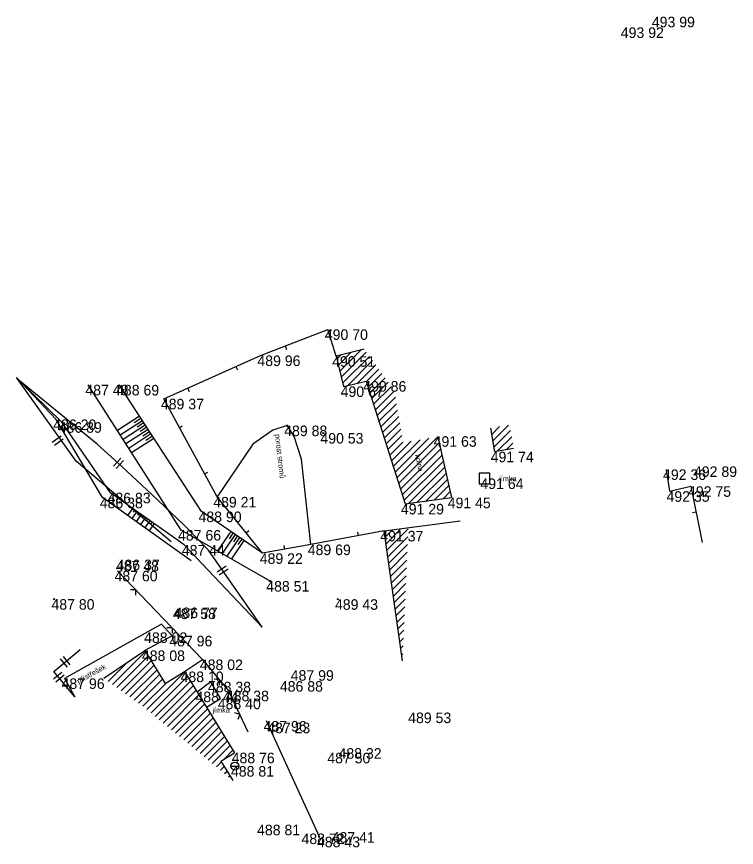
# Model space of a CAD drawing. Extents: x -553666 to -553461, y -1076543 to -1076230.
# Drawn here: x -553529.6 to -553461.3, y -1076543.4 to -1076464.6 of the extents above; entities that cross this region are included whole.
import ezdxf

# ---------------------------------------------------------------- set-up
doc = ezdxf.new("R2010")
doc.units = 0
for name, color, linetype in [('1', 7, 'Continuous'), ('12', 7, 'Continuous'), ('14', 7, 'Continuous'), ('18', 7, 'Continuous'), ('26', 7, 'Continuous'), ('27', 7, 'Continuous'), ('28', 7, 'Continuous'), ('32', 7, 'Continuous'), ('34', 7, 'Continuous'), ('50', 7, 'Continuous'), ('52', 7, 'Continuous'), ('6', 7, 'Continuous'), ('62', 7, 'Continuous')]:
    doc.layers.add(name, color=color, linetype=linetype)

# ---------------------------------------------------------------- blocks, each defined once
blk = doc.blocks.new('POINT_DISPLAY')
blk.add_line((0, 0), (0, 0))
blk = doc.blocks.new('T')
at = {"layer": '6'}
blk.add_circle((0, 0), 0.05, dxfattribs=at)
blk = doc.blocks.new('ST')
at = {"layer": '1'}
blk.add_line((-0.375, 0), (0.375, 0), dxfattribs=at)
blk.add_circle((0, 0), 0.375, dxfattribs=at)
blk = doc.blocks.new('SA')
at = {"layer": '50'}
blk.add_lwpolyline([(-0.5, -0.5), (0.5, -0.5), (0.5, 0.5), (-0.5, 0.5)], close=True, dxfattribs=at)
blk = doc.blocks.new('ROV')
at = {"layer": '62'}
for p, q in [((-0.348, -0.51), (-0.348, 0.51)), ((0, -0.51), (0, 0.51))]:
    blk.add_line(p, q, dxfattribs=at)

msp = doc.modelspace()

# ---------------------------------------------------------------- linework, layer by layer
at = {"layer": '12'}
for p, q in [((-553506.44, -1076496.75), (-553500.06, -1076494.27)), ((-553499.26, -1076496.82), (-553500.06, -1076494.27)), ((-553500.008, -1076494.435), (-553499.674, -1076494.33)), ((-553504.11, -1076495.844), (-553503.983, -1076496.17)), ((-553515.63, -1076500.86), (-553506.44, -1076496.75)), ((-553508.783, -1076497.798), (-553508.641, -1076498.118)), ((-553513.348, -1076499.839), (-553513.205, -1076500.159)), ((-553510.55, -1076510.17), (-553515.63, -1076500.86)), ((-553514.142, -1076503.586), (-553513.835, -1076503.419)), ((-553511.747, -1076507.975), (-553511.44, -1076507.808)), ((-553467.94, -1076507.56), (-553467.62, -1076509.63)), ((-553467.62, -1076509.63), (-553465.58, -1076509.16)), ((-553465.58, -1076509.16), (-553464.513, -1076514.499)), ((-553506.24, -1076515.52), (-553510.55, -1076510.17)), ((-553465.09, -1076511.612), (-553465.433, -1076511.68)), ((-553507.808, -1076513.573), (-553507.536, -1076513.354)), ((-553494.69, -1076513.39), (-553501.66, -1076514.69)), ((-553497.148, -1076513.848), (-553497.212, -1076513.504)), ((-553501.66, -1076514.69), (-553506.24, -1076515.52)), ((-553504.12, -1076515.136), (-553504.182, -1076514.791)), ((-553520.03, -1076517.18), (-553511.94, -1076525.6)), ((-553518.298, -1076518.983), (-553518.798, -1076518.973)), ((-553518.298, -1076518.983), (-553518.308, -1076519.483)), ((-553514.834, -1076522.588), (-553515.334, -1076522.578)), ((-553514.834, -1076522.588), (-553514.844, -1076523.089)), ((-553513.66, -1076526.74), (-553511.94, -1076525.6)), ((-553511.94, -1076525.6), (-553509.47, -1076528.56)), ((-553510.338, -1076527.519), (-553510.837, -1076527.474)), ((-553510.338, -1076527.519), (-553510.383, -1076528.018)), ((-553509.47, -1076528.56), (-553507.66, -1076532.46)), ((-553508.418, -1076530.828), (-553508.888, -1076530.656)), ((-553508.418, -1076530.828), (-553508.59, -1076531.298))]:
    msp.add_line(p, q, dxfattribs=at)
at = {"layer": '14'}
for p, q in [((-553496.592, -1076496.158), (-553499.26, -1076496.82)), ((-553499.26, -1076496.82), (-553498.55, -1076499.68)), ((-553498.55, -1076499.68), (-553496.4, -1076499.18)), ((-553496.4, -1076499.18), (-553492.72, -1076510.83)), ((-553484.594, -1076503.634), (-553484.22, -1076505.88)), ((-553489.597, -1076504.468), (-553488.3, -1076510.24)), ((-553482.409, -1076505.578), (-553484.22, -1076505.88)), ((-553492.72, -1076510.83), (-553488.3, -1076510.24)), ((-553494.69, -1076513.39), (-553487.47, -1076512.44)), ((-553492.965, -1076525.737), (-553494.69, -1076513.39)), ((-553521.317, -1076527.375), (-553517.44, -1076524.74)), ((-553517.44, -1076524.74), (-553515.504, -1076527.878)), ((-553515.504, -1076527.878), (-553513.66, -1076526.74)), ((-553513.66, -1076526.74), (-553508.91, -1076534.44)), ((-553510.204, -1076535.238), (-553508.91, -1076534.44)), ((-553510.204, -1076535.238), (-553509.081, -1076537.062))]:
    msp.add_line(p, q, dxfattribs=at)
at = {"layer": '18'}
for p, q in [((-553515.834, -1076522.24), (-553525.05, -1076527.39)), ((-553514.82, -1076523.35), (-553515.834, -1076522.24)), ((-553514.82, -1076523.35), (-553517.44, -1076524.74)), ((-553525.05, -1076527.39), (-553524.07, -1076529.13)), ((-553511.17, -1076527.71), (-553512.453, -1076528.696)), ((-553510.25, -1076529.31), (-553511.17, -1076527.71)), ((-553511.572, -1076530.125), (-553510.25, -1076529.31))]:
    msp.add_line(p, q, dxfattribs=at)
at = {"layer": '26'}
for p, q in [((-553517.933, -1076502.518), (-553520.031, -1076503.883)), ((-553517.796, -1076502.727), (-553518.426, -1076503.137)), ((-553517.66, -1076502.937), (-553519.761, -1076504.304)), ((-553517.387, -1076503.356), (-553519.491, -1076504.725)), ((-553517.524, -1076503.146), (-553518.154, -1076503.557)), ((-553517.251, -1076503.566), (-553517.883, -1076503.977)), ((-553517.115, -1076503.775), (-553519.222, -1076505.146)), ((-553516.842, -1076504.194), (-553518.952, -1076505.567)), ((-553516.978, -1076503.985), (-553517.611, -1076504.396)), ((-553516.569, -1076504.613), (-553518.682, -1076505.988)), ((-553516.706, -1076504.404), (-553517.339, -1076504.816)), ((-553518.591, -1076511.262), (-553519.062, -1076511.929)), ((-553518.387, -1076511.406), (-553518.529, -1076511.607)), ((-553518.183, -1076511.551), (-553518.655, -1076512.219)), ((-553517.774, -1076511.839), (-553518.247, -1076512.51)), ((-553517.978, -1076511.695), (-553518.12, -1076511.896)), ((-553517.366, -1076512.127), (-553517.841, -1076512.799)), ((-553517.57, -1076511.983), (-553517.712, -1076512.184)), ((-553516.957, -1076512.416), (-553517.433, -1076513.09)), ((-553517.162, -1076512.272), (-553517.304, -1076512.473)), ((-553516.549, -1076512.704), (-553517.026, -1076513.38)), ((-553516.753, -1076512.56), (-553516.896, -1076512.762)), ((-553509.263, -1076513.459), (-553510.516, -1076515.297)), ((-553508.85, -1076513.741), (-553510.081, -1076515.547)), ((-553509.057, -1076513.6), (-553509.429, -1076514.147)), ((-553508.437, -1076514.023), (-553509.645, -1076515.796)), ((-553508.024, -1076514.304), (-553509.21, -1076516.044)), ((-553508.644, -1076513.882), (-553509.009, -1076514.419)), ((-553508.23, -1076514.163), (-553508.59, -1076514.69))]:
    msp.add_line(p, q, dxfattribs=at)
at = {"layer": '27'}
for p, q in [((-553525.31, -1076503.08), (-553529.35, -1076499.11)), ((-553513.99, -1076513.31), (-553522.82, -1076499.53)), ((-553512.05, -1076511.56), (-553519.87, -1076499.54)), ((-553520.69, -1076509.78), (-553525.31, -1076503.08)), ((-553513.68, -1076514.73), (-553520.69, -1076509.78)), ((-553506.24, -1076515.52), (-553512.05, -1076511.56)), ((-553505.53, -1076518.15), (-553513.99, -1076513.31)), ((-553506.27, -1076522.52), (-553513.68, -1076514.73)), ((-553500.83, -1076542.41), (-553505.87, -1076531.43))]:
    msp.add_line(p, q, dxfattribs=at)
at = {"layer": '28'}
for p, q in [((-553525.85, -1076502.82), (-553529.6, -1076498.84)), ((-553521.43, -1076510.24), (-553525.85, -1076502.82)), ((-553513.03, -1076516.23), (-553521.43, -1076510.24))]:
    msp.add_line(p, q, dxfattribs=at)
at = {"layer": '32'}
for p, q in [((-553499.052, -1076497.659), (-553497.867, -1076496.474)), ((-553498.911, -1076498.226), (-553496.926, -1076496.241)), ((-553498.77, -1076498.792), (-553496.4, -1076496.422)), ((-553499.192, -1076497.093), (-553498.807, -1076496.708)), ((-553498.63, -1076499.359), (-553496.102, -1076496.831)), ((-553498.151, -1076499.587), (-553495.804, -1076497.24)), ((-553497.23, -1076499.373), (-553495.507, -1076497.65)), ((-553496.383, -1076499.233), (-553495.209, -1076498.059)), ((-553496.213, -1076499.771), (-553494.911, -1076498.468)), ((-553496.044, -1076500.308), (-553494.613, -1076498.877)), ((-553495.874, -1076500.845), (-553494.315, -1076499.287)), ((-553495.704, -1076501.383), (-553494.017, -1076499.696)), ((-553495.534, -1076501.92), (-553493.728, -1076500.113)), ((-553495.365, -1076502.458), (-553493.627, -1076500.72)), ((-553495.195, -1076502.995), (-553493.526, -1076501.326)), ((-553495.025, -1076503.532), (-553493.425, -1076501.932)), ((-553494.855, -1076504.07), (-553493.324, -1076502.538)), ((-553494.686, -1076504.607), (-553493.223, -1076503.144)), ((-553484.493, -1076504.24), (-553483.745, -1076503.492)), ((-553484.392, -1076504.846), (-553482.897, -1076503.351)), ((-553494.516, -1076505.144), (-553493.122, -1076503.75)), ((-553494.346, -1076505.682), (-553493.021, -1076504.356)), ((-553484.291, -1076505.453), (-553482.696, -1076503.857)), ((-553494.176, -1076506.219), (-553492.92, -1076504.962)), ((-553494.007, -1076506.756), (-553492.142, -1076504.892)), ((-553493.837, -1076507.294), (-553491.294, -1076504.751)), ((-553493.667, -1076507.831), (-553490.445, -1076504.609)), ((-553493.498, -1076508.369), (-553489.597, -1076504.468)), ((-553493.328, -1076508.906), (-553489.467, -1076505.045)), ((-553483.97, -1076505.838), (-553482.595, -1076504.463)), ((-553483.121, -1076505.697), (-553482.494, -1076505.069)), ((-553493.158, -1076509.443), (-553489.338, -1076505.623)), ((-553492.988, -1076509.981), (-553489.208, -1076506.2)), ((-553492.819, -1076510.518), (-553489.078, -1076506.777)), ((-553492.378, -1076510.784), (-553488.948, -1076507.355)), ((-553491.562, -1076510.675), (-553488.819, -1076507.932)), ((-553490.746, -1076510.566), (-553488.689, -1076508.51)), ((-553489.93, -1076510.458), (-553488.559, -1076509.087)), ((-553489.114, -1076510.349), (-553488.429, -1076509.664)), ((-553494.606, -1076513.989), (-553493.948, -1076513.331)), ((-553494.52, -1076514.61), (-553493.179, -1076513.269)), ((-553494.433, -1076515.23), (-553492.411, -1076513.208)), ((-553494.346, -1076515.85), (-553492.444, -1076513.948)), ((-553494.26, -1076516.471), (-553492.476, -1076514.688)), ((-553494.173, -1076517.091), (-553492.509, -1076515.427)), ((-553494.086, -1076517.712), (-553492.542, -1076516.167)), ((-553494, -1076518.332), (-553492.575, -1076516.907)), ((-553493.913, -1076518.953), (-553492.607, -1076517.647)), ((-553493.826, -1076519.573), (-553492.64, -1076518.387)), ((-553493.74, -1076520.193), (-553492.673, -1076519.127)), ((-553493.653, -1076520.814), (-553492.705, -1076519.866)), ((-553493.566, -1076521.434), (-553492.738, -1076520.606)), ((-553493.479, -1076522.055), (-553492.771, -1076521.346)), ((-553493.393, -1076522.675), (-553492.804, -1076522.086)), ((-553493.306, -1076523.295), (-553492.836, -1076522.826)), ((-553493.219, -1076523.916), (-553492.869, -1076523.565)), ((-553520.495, -1076527.967), (-553517.374, -1076524.847)), ((-553493.133, -1076524.536), (-553492.902, -1076524.305)), ((-553520.083, -1076528.263), (-553517.104, -1076525.284)), ((-553493.046, -1076525.157), (-553492.934, -1076525.045)), ((-553520.906, -1076527.671), (-553519.11, -1076525.875)), ((-553519.672, -1076528.558), (-553516.835, -1076525.721)), ((-553519.261, -1076528.854), (-553516.565, -1076526.158)), ((-553518.85, -1076529.15), (-553516.295, -1076526.596)), ((-553518.438, -1076529.446), (-553516.025, -1076527.033)), ((-553517.223, -1076530.352), (-553513.641, -1076526.77)), ((-553516.835, -1076530.671), (-553513.371, -1076527.208)), ((-553518.027, -1076529.742), (-553515.755, -1076527.47)), ((-553517.616, -1076530.038), (-553515.379, -1076527.801)), ((-553516.447, -1076530.991), (-553513.102, -1076527.645)), ((-553516.06, -1076531.31), (-553512.832, -1076528.082)), ((-553515.672, -1076531.63), (-553512.562, -1076528.52)), ((-553515.284, -1076531.949), (-553512.292, -1076528.957)), ((-553514.897, -1076532.269), (-553512.023, -1076529.394)), ((-553514.509, -1076532.588), (-553511.753, -1076529.832)), ((-553514.122, -1076532.908), (-553511.483, -1076530.269)), ((-553513.734, -1076533.227), (-553511.213, -1076530.706)), ((-553513.346, -1076533.546), (-553510.943, -1076531.144)), ((-553512.959, -1076533.866), (-553510.674, -1076531.581)), ((-553512.571, -1076534.185), (-553510.404, -1076532.018)), ((-553512.183, -1076534.505), (-553510.134, -1076532.456)), ((-553511.796, -1076534.824), (-553509.864, -1076532.893)), ((-553511.408, -1076535.144), (-553509.595, -1076533.33)), ((-553511.021, -1076535.463), (-553509.325, -1076533.768)), ((-553509.902, -1076535.052), (-553509.055, -1076534.205)), ((-553510.633, -1076535.783), (-553510.16, -1076535.31)), ((-553510.245, -1076536.102), (-553509.89, -1076535.747)), ((-553509.858, -1076536.422), (-553509.621, -1076536.185)), ((-553509.47, -1076536.741), (-553509.351, -1076536.623)), ((-553509.082, -1076537.061), (-553509.082, -1076537.06))]:
    msp.add_line(p, q, dxfattribs=at)
at = {"layer": '34'}
for points in [[(-553503.92, -1076503.4), (-553505.28, -1076503.851), (-553507.164, -1076505.162), (-553510.55, -1076510.17)], [(-553501.66, -1076514.69), (-553502.548, -1076506.582), (-553503.258, -1076504.452), (-553503.92, -1076503.4)]]:
    msp.add_lwpolyline(points, dxfattribs=at)
at = {"layer": '62'}
for p, q in [((-553523.93, -1076506.79), (-553529.6, -1076498.84)), ((-553521.94, -1076505.15), (-553529.35, -1076499.11)), ((-553519.6, -1076507.279), (-553521.94, -1076505.15)), ((-553514.917, -1076514.416), (-553523.93, -1076506.79)), ((-553516.751, -1076509.93), (-553519.6, -1076507.279)), ((-553513.789, -1076512.751), (-553516.751, -1076509.93)), ((-553511.37, -1076515.22), (-553513.789, -1076512.751)), ((-553506.27, -1076522.52), (-553511.37, -1076515.22)), ((-553526.06, -1076526.72), (-553523.561, -1076524.657)), ((-553524.07, -1076529.13), (-553526.06, -1076526.72))]:
    msp.add_line(p, q, dxfattribs=at)

# ---------------------------------------------------------------- block references
at = {"layer": '1'}
for name, p in [('POINT_DISPLAY', (-553468.99, -1076464.61)), ('POINT_DISPLAY', (-553471.95, -1076465.62)), ('POINT_DISPLAY', (-553500.06, -1076494.27)), ('POINT_DISPLAY', (-553506.44, -1076496.75)), ('POINT_DISPLAY', (-553499.26, -1076496.82)), ('POINT_DISPLAY', (-553522.82, -1076499.53)), ('POINT_DISPLAY', (-553519.87, -1076499.54)), ('POINT_DISPLAY', (-553496.4, -1076499.18)), ('POINT_DISPLAY', (-553498.55, -1076499.68)), ('POINT_DISPLAY', (-553515.63, -1076500.86)), ('POINT_DISPLAY', (-553525.85, -1076502.82)), ('POINT_DISPLAY', (-553525.31, -1076503.08)), ('POINT_DISPLAY', (-553503.92, -1076503.4)), ('POINT_DISPLAY', (-553500.48, -1076504.11)), ('POINT_DISPLAY', (-553492.87, -1076504.98)), ('POINT_DISPLAY', (-553489.61, -1076504.41)), ('POINT_DISPLAY', (-553484.22, -1076505.88)), ('POINT_DISPLAY', (-553465, -1076507.27)), ('POINT_DISPLAY', (-553467.94, -1076507.56)), ('POINT_DISPLAY', (-553485.18, -1076508.42)), ('POINT_DISPLAY', (-553520.69, -1076509.78)), ('POINT_DISPLAY', (-553467.62, -1076509.63)), ('POINT_DISPLAY', (-553465.58, -1076509.16)), ('POINT_DISPLAY', (-553521.43, -1076510.24)), ('POINT_DISPLAY', (-553510.55, -1076510.17)), ('POINT_DISPLAY', (-553488.3, -1076510.24)), ('POINT_DISPLAY', (-553492.72, -1076510.83)), ('POINT_DISPLAY', (-553512.05, -1076511.56)), ('POINT_DISPLAY', (-553513.99, -1076513.31)), ('POINT_DISPLAY', (-553494.69, -1076513.39)), ('POINT_DISPLAY', (-553513.68, -1076514.73)), ('POINT_DISPLAY', (-553501.66, -1076514.69)), ('POINT_DISPLAY', (-553519.83, -1076516.12)), ('POINT_DISPLAY', (-553506.24, -1076515.52)), ('POINT_DISPLAY', (-553519.93, -1076516.24)), ('POINT_DISPLAY', (-553520.03, -1076517.18)), ('POINT_DISPLAY', (-553505.53, -1076518.15)), ('POINT_DISPLAY', (-553526.03, -1076519.87)), ('POINT_DISPLAY', (-553499.11, -1076519.88)), ('POINT_DISPLAY', (-553514.51, -1076520.76)), ('POINT_DISPLAY', (-553514.33, -1076520.67)), ('POINT_DISPLAY', (-553517.23, -1076523.02)), ('POINT_DISPLAY', (-553514.82, -1076523.35)), ('POINT_DISPLAY', (-553517.44, -1076524.74)), ('POINT_DISPLAY', (-553511.94, -1076525.6)), ('POINT_DISPLAY', (-553513.66, -1076526.74)), ('POINT_DISPLAY', (-553503.29, -1076526.61)), ('POINT_DISPLAY', (-553525.05, -1076527.39)), ('POINT_DISPLAY', (-553511.17, -1076527.71)), ('POINT_DISPLAY', (-553504.33, -1076527.65)), ('POINT_DISPLAY', (-553512.38, -1076528.64)), ('POINT_DISPLAY', (-553509.47, -1076528.56)), ('POINT_DISPLAY', (-553510.25, -1076529.31)), ('POINT_DISPLAY', (-553492.15, -1076530.63)), ('POINT_DISPLAY', (-553505.87, -1076531.43)), ('POINT_DISPLAY', (-553505.55, -1076531.59)), ('POINT_DISPLAY', (-553498.77, -1076534.01)), ('POINT_DISPLAY', (-553508.91, -1076534.44)), ('POINT_DISPLAY', (-553499.84, -1076534.45)), ('ST', (-553508.88, -1076535.71)), ('POINT_DISPLAY', (-553508.88, -1076535.71)), ('POINT_DISPLAY', (-553506.4, -1076541.27)), ('POINT_DISPLAY', (-553502.29, -1076542.11)), ('POINT_DISPLAY', (-553499.33, -1076541.98)), ('POINT_DISPLAY', (-553500.83, -1076542.41))]:
    msp.add_blockref(name, p, dxfattribs=at)
at = {"layer": '32'}
for p in [(-553484.594, -1076503.634), (-553489.597, -1076504.468), (-553492.411, -1076513.208), (-553521.317, -1076527.375)]:
    msp.add_blockref('POINT_DISPLAY', p, dxfattribs=at)
at = {"layer": '50'}
msp.add_blockref('SA', (-553485.18, -1076508.42), dxfattribs=at)
at = {"layer": '6'}
for p in [(-553503.92, -1076503.4), (-553500.48, -1076504.11), (-553505.53, -1076518.15), (-553526.03, -1076519.87), (-553499.11, -1076519.88)]:
    msp.add_blockref('T', p, dxfattribs=at)
at = {"layer": '62'}
for p, xscale, yscale, rotation in [((-553525.796, -1076504.71), 1.000001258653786, 1.0000012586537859, 125.49673748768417), ((-553519.793, -1076507.103), 0.9999980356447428, 0.9999980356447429, -42.29682302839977), ((-553509.937, -1076517.271), 1.000001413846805, 1.000001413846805, -55.06074372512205), ((-553524.834, -1076525.708), 1.0000002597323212, 1.0000002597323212, 39.54061871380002), ((-553525.707, -1076527.148), 1.0000021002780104, 1.0000021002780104, 129.5474514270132)]:
    msp.add_blockref('ROV', p, dxfattribs=dict(at, xscale=xscale, yscale=yscale, rotation=rotation))

# ---------------------------------------------------------------- texts
at = {"layer": '52'}
for s, rotation, p in [('porost stromů', 276.25021, (-553505.067, -1076504.23)), ('kolna', 282.66432, (-553491.801, -1076506.189)), ('přístřešek', 29.19693, (-553523.704, -1076527.911))]:
    msp.add_text(s, height=0.5, rotation=rotation, dxfattribs=at).set_placement(p)
for p in [(-553483.78, -1076508.683), (-553511.004, -1076530.648)]:
    msp.add_text('jímka', height=0.5, dxfattribs=at).set_placement(p)
at = {"layer": '6'}
for s, p in [('493 99 ', (-553469.288, -1076465.61)), ('493 92 ', (-553472.236, -1076466.62)), ('490 70 ', (-553500.336, -1076495.27)), ('489 96 ', (-553506.738, -1076497.75)), ('490 51 ', (-553499.643, -1076497.82)), ('487 48 ', (-553523.068, -1076500.53)), ('488 69 ', (-553520.156, -1076500.54)), ('490 86 ', (-553496.688, -1076500.18)), ('490 67 ', (-553498.836, -1076500.68)), ('489 37 ', (-553515.902, -1076501.86)), ('486 20 ', (-553526.126, -1076503.82)), ('486 89 ', (-553525.596, -1076504.08)), ('489 88 ', (-553504.194, -1076504.4)), ('490 53 ', (-553500.756, -1076505.11)), ('491 63 ', (-553490.005, -1076505.41)), ('491 74 ', (-553484.589, -1076506.88)), ('492 89 ', (-553465.286, -1076508.27)), ('492 36 ', (-553468.226, -1076508.56)), ('491 64 ', (-553485.563, -1076509.42)), ('486 83 ', (-553520.964, -1076510.78)), ('492 35 ', (-553467.894, -1076510.63)), ('492 75 ', (-553465.852, -1076510.16)), ('486 38 ', (-553521.704, -1076511.24)), ('489 21 ', (-553510.931, -1076511.17)), ('491 45 ', (-553488.671, -1076511.24)), ('491 29 ', (-553493.115, -1076511.83)), ('488 90 ', (-553512.326, -1076512.56)), ('487 66 ', (-553514.274, -1076514.31)), ('491 37 ', (-553495.071, -1076514.39)), ('487 44 ', (-553513.916, -1076515.73)), ('489 69 ', (-553501.958, -1076515.69)), ('486 37 ', (-553520.102, -1076517.12)), ('489 22 ', (-553506.514, -1076516.52)), ('487 48 ', (-553520.178, -1076517.24)), ('487 60 ', (-553520.304, -1076518.18)), ('488 51 ', (-553505.899, -1076519.15)), ('487 80 ', (-553526.292, -1076520.87)), ('489 43 ', (-553499.372, -1076520.88)), ('487 58 ', (-553514.77, -1076521.76)), ('486 77 ', (-553514.6, -1076521.67)), ('488 02 ', (-553517.494, -1076524.02)), ('487 96 ', (-553515.104, -1076524.35)), ('488 08 ', (-553517.704, -1076525.74)), ('488 02 ', (-553512.204, -1076526.6)), ('488 10 ', (-553514.033, -1076527.74)), ('487 99 ', (-553503.574, -1076527.61)), ('487 96 ', (-553525.334, -1076528.39)), ('488 38 ', (-553511.432, -1076528.71)), ('486 88 ', (-553504.604, -1076528.65)), ('488 44 ', (-553512.618, -1076529.64)), ('488 38 ', (-553509.732, -1076529.56)), ('488 40 ', (-553510.502, -1076530.31)), ('489 53 ', (-553492.424, -1076531.63)), ('487 96 ', (-553506.154, -1076532.43)), ('487 23 ', (-553505.81, -1076532.59)), ('488 32 ', (-553499.032, -1076535.01)), ('488 76 ', (-553509.182, -1076535.44)), ('487 50 ', (-553500.102, -1076535.45)), ('488 81 ', (-553509.249, -1076536.71)), ('488 81 ', (-553506.769, -1076542.27)), ('488 72 ', (-553502.55, -1076543.11)), ('487 41 ', (-553499.685, -1076542.98)), ('488 43 ', (-553501.08, -1076543.41))]:
    msp.add_text(s, height=1, dxfattribs=at).set_placement(p)

doc.saveas('drawing.dxf')
